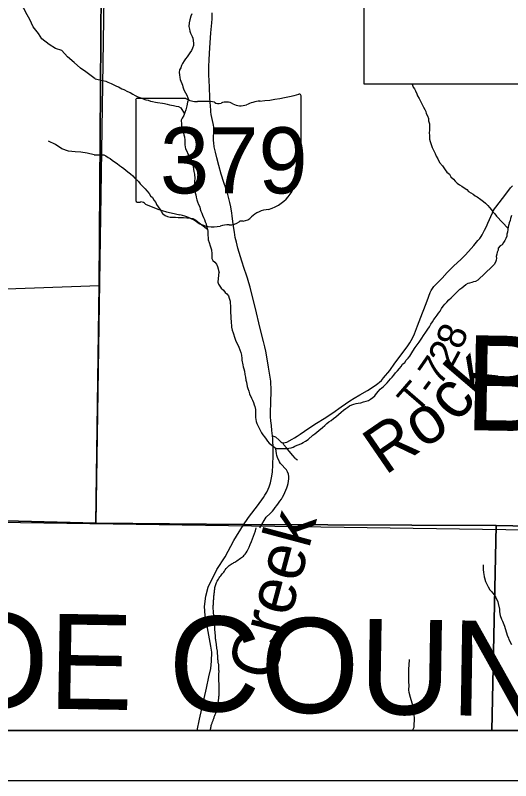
# Model space of a CAD drawing. Extents: x 0 to 34, y 0 to 22.
# Drawn here: x 26.845 to 27.832, y 14 to 15.526 of the extents above; entities that cross this region are included whole.
import ezdxf

# ---------------------------------------------------------------- set-up
doc = ezdxf.new("R2010")
doc.units = 0
for name, color, linetype in [('GM_X_Corporation', 7, 'Continuous'), ('GM_X_County', 7, 'Continuous'), ('GM_X_County_Text', 7, 'Continuous'), ('GM_X_Minor_River', 7, 'Continuous'), ('GM_X_Minor_River_Text', 7, 'Continuous'), ('GM_X_State_Route', 7, 'Continuous'), ('GM_X_State_Shield', 7, 'Continuous'), ('GM_X_Township_Road', 7, 'Continuous'), ('GM_X_Township_Road_Text', 7, 'Continuous'), ('SH_Data', 7, 'Continuous')]:
    doc.layers.add(name, color=color, linetype=linetype)

msp = doc.modelspace()

# ---------------------------------------------------------------- linework, layer by layer
at = {"layer": 'GM_X_Corporation'}
for points in [[(30.3167, 20.9), (27.1022, 20.9), (27.0898, 20.417), (27.0897, 20.4135), (27.089, 20.3692), (27.0873, 20.2665), (27.0907, 20.123), (27.0885, 20.1139), (27.0864, 20.0138), (27.0761, 19.6806), (27.0733, 19.498), (27.0719, 19.3912), (27.0487, 18.5805), (27.0419, 17.8236), (27.0349, 17.5522), (27.0234, 16.6611), (27.0124, 14.988), (27.0057, 14.5136), (27.2999, 14.5107), (27.8031, 14.5091), (28.4032, 14.497)], [(29.5503, 20.3788), (27.6751, 20.4106), (27.5829, 20.4116), (27.2336, 20.4152), (27.1239, 20.4163), (27.0898, 20.417), (27.0897, 20.4135), (27.089, 20.3692), (27.0873, 20.2665), (27.0907, 20.123), (27.0885, 20.1139), (27.0864, 20.0138), (27.0761, 19.6806), (27.0733, 19.498), (27.0719, 19.3912), (27.0487, 18.5805), (27.0419, 17.8236), (27.0349, 17.5522), (27.0234, 16.6611), (27.0124, 14.988), (27.0057, 14.5136), (27.2999, 14.5107), (27.8031, 14.5091), (28.4032, 14.497)], [(23.5167, 20.3276), (23.5167, 14.5642), (23.7464, 14.562), (24.4108, 14.5557), (24.414, 14.5556), (24.9788, 14.5503), (25.0494, 14.5496), (25.56, 14.5392), (26.009, 14.53), (26.3333, 14.5233), (26.7998, 14.5186), (27.0057, 14.5136), (27.0124, 14.988), (27.0234, 16.6611), (27.0349, 17.5522)], [(23.5167, 20.3276), (23.5167, 14.5642), (23.7464, 14.562), (24.4108, 14.5557), (24.414, 14.5556), (24.9788, 14.5503), (25.0494, 14.5496), (25.56, 14.5392), (26.009, 14.53), (26.3333, 14.5233), (26.7998, 14.5186), (27.0057, 14.5136), (27.0124, 14.988), (27.0234, 16.6611), (27.0349, 17.5522)]]:
    msp.add_lwpolyline(points, dxfattribs=at)
for points in [[(23.5167, 14.5642), (23.5167, 14.1), (30.3167, 14.1), (30.3167, 14.4639), (30.3098, 14.464), (29.2367, 14.4822), (29.1713, 14.4832), (28.7853, 14.4893), (28.4032, 14.497), (27.8031, 14.5091), (27.2999, 14.5107), (27.0057, 14.5136), (26.7998, 14.5186), (26.3333, 14.5233), (26.009, 14.53), (25.56, 14.5392), (25.0494, 14.5496), (24.9788, 14.5503), (24.414, 14.5556), (24.4108, 14.5557), (23.7464, 14.562)], [(23.5167, 14.5642), (23.5167, 14.1), (27.795, 14.1), (27.8031, 14.5091), (27.2999, 14.5107), (27.0057, 14.5136), (26.7998, 14.5186), (26.3333, 14.5233), (26.009, 14.53), (25.56, 14.5392), (25.0494, 14.5496), (24.9788, 14.5503), (24.414, 14.5556), (24.4108, 14.5557), (23.7464, 14.562)], [(27.795, 14.1), (30.3167, 14.1), (30.3167, 14.4639), (30.3098, 14.464), (29.2367, 14.4822), (29.1713, 14.4832), (28.7853, 14.4893), (28.4032, 14.497), (27.8031, 14.5091)]]:
    msp.add_lwpolyline(points, close=True, dxfattribs=at)
at = {"layer": 'GM_X_County'}
for p, q in [((27.1022, 20.9), (27.0057, 14.5136)), ((23.5167, 14.5642), (30.3167, 14.4639))]:
    msp.add_line(p, q, dxfattribs=at)
at = {"layer": 'GM_X_Minor_River'}
for points in [[(27.0043, 15.3997), (26.9854, 15.4131), (26.975, 15.4209), (26.9624, 15.4322), (26.949, 15.4434), (26.9376, 15.4557), (26.9254, 15.4601), (26.9124, 15.4679), (26.8983, 15.4795), (26.8914, 15.4896), (26.8806, 15.5032), (26.874, 15.5175), (26.869, 15.5273), (26.8616, 15.5408), (26.8536, 15.5506)], [(27.1969, 15.5291), (27.1951, 15.5241), (27.1933, 15.5169), (27.1919, 15.5108), (27.1912, 15.5036), (27.1921, 15.4983), (27.1933, 15.4945), (27.1945, 15.4904), (27.1973, 15.484), (27.1988, 15.4802), (27.2005, 15.4708), (27.2002, 15.4659), (27.1984, 15.4609), (27.1962, 15.4556), (27.1929, 15.4513), (27.1874, 15.4436), (27.1844, 15.4394), (27.1818, 15.4356), (27.1781, 15.4302), (27.1763, 15.426), (27.1749, 15.4214), (27.1727, 15.4176), (27.1716, 15.4119), (27.1721, 15.4077), (27.173, 15.4021), (27.1738, 15.3983), (27.1781, 15.387), (27.179, 15.3832), (27.181, 15.3772), (27.1841, 15.3716), (27.1872, 15.3667), (27.1892, 15.3618), (27.1904, 15.358), (27.1886, 15.3531), (27.1868, 15.3458), (27.185, 15.3375), (27.1832, 15.3321), (27.1811, 15.3264), (27.1778, 15.3207), (27.1759, 15.3168), (27.1761, 15.3089), (27.1765, 15.3047), (27.1777, 15.3009), (27.1789, 15.2968), (27.181, 15.2877), (27.1822, 15.2836), (27.1827, 15.2772), (27.1831, 15.2726), (27.1832, 15.2681), (27.1841, 15.2601), (27.1869, 15.2549), (27.1892, 15.2496), (27.1916, 15.2458), (27.1943, 15.2417), (27.1967, 15.2349), (27.1987, 15.2285), (27.1995, 15.2248), (27.2003, 15.2191), (27.2012, 15.2146), (27.202, 15.2093), (27.2029, 15.2006), (27.2026, 15.1956), (27.202, 15.1884), (27.2029, 15.1816), (27.2033, 15.1778), (27.2038, 15.1721), (27.205, 15.168), (27.2055, 15.1635), (27.2071, 15.1582), (27.2083, 15.154), (27.2103, 15.1488), (27.2126, 15.1442), (27.2135, 15.1397), (27.215, 15.1356)], [(27.0043, 15.3997), (27.0198, 15.396), (27.0255, 15.3946), (27.0293, 15.3931), (27.0362, 15.3898), (27.0469, 15.3851), (27.0511, 15.3833), (27.0576, 15.3796), (27.0614, 15.3781), (27.0686, 15.3745), (27.0743, 15.3719), (27.0793, 15.369), (27.0839, 15.3664), (27.0896, 15.3638), (27.0953, 15.3613), (27.0999, 15.3595), (27.1052, 15.3577), (27.1098, 15.3566), (27.1144, 15.3552), (27.1185, 15.3545), (27.1246, 15.3531), (27.1284, 15.3524), (27.1387, 15.3507), (27.1428, 15.3504), (27.1478, 15.3489), (27.1527, 15.3479), (27.1565, 15.3472), (27.1607, 15.3461), (27.1656, 15.3451), (27.1706, 15.344), (27.1748, 15.3415), (27.1823, 15.3296)], [(27.6357, 15.3888), (27.6367, 15.3871), (27.638, 15.383), (27.6407, 15.3792), (27.6426, 15.3755), (27.645, 15.3698), (27.6466, 15.3657), (27.6497, 15.36), (27.6528, 15.3548), (27.6548, 15.3507), (27.6587, 15.3431), (27.6611, 15.3383), (27.663, 15.3345), (27.6642, 15.33), (27.6669, 15.3258), (27.6686, 15.3202), (27.6686, 15.3156), (27.6703, 15.3096), (27.6707, 15.3058), (27.6708, 15.3013), (27.6705, 15.2963), (27.6702, 15.2922), (27.6703, 15.2861), (27.6704, 15.2793), (27.672, 15.2748), (27.6732, 15.2702), (27.6756, 15.2623), (27.6819, 15.2503), (27.6839, 15.245), (27.687, 15.2398), (27.6905, 15.2323), (27.6967, 15.2263), (27.7021, 15.218), (27.7052, 15.2132), (27.7102, 15.2091), (27.7133, 15.2038), (27.7183, 15.1994), (27.7214, 15.1956), (27.7257, 15.1916), (27.7306, 15.1882), (27.7348, 15.1856), (27.7394, 15.1823), (27.7448, 15.1786), (27.7486, 15.1749), (27.7578, 15.1697), (27.7617, 15.166), (27.7655, 15.1642), (27.7728, 15.159), (27.7781, 15.1546), (27.7824, 15.1512)], [(27.0026, 15.248), (26.9885, 15.2509), (26.976, 15.253), (26.9642, 15.254), (26.951, 15.2554), (26.9377, 15.2598), (26.9251, 15.2683), (26.9114, 15.275)], [(27.0026, 15.248), (27.0216, 15.2478), (27.0254, 15.2456), (27.03, 15.2423), (27.0339, 15.2404), (27.0385, 15.2371), (27.0427, 15.2341), (27.0484, 15.2304), (27.053, 15.2267), (27.0569, 15.2238), (27.0614, 15.2208), (27.0657, 15.2175), (27.0695, 15.2141), (27.0749, 15.2097), (27.0791, 15.2063), (27.083, 15.2022), (27.091, 15.1944), (27.0941, 15.1903), (27.0984, 15.1855), (27.1038, 15.1799), (27.1076, 15.1758), (27.1119, 15.1709), (27.1146, 15.166), (27.1185, 15.1627), (27.1216, 15.1571), (27.1254, 15.1526), (27.1266, 15.1488), (27.1297, 15.1443), (27.1329, 15.1394), (27.1356, 15.1353), (27.1387, 15.1312), (27.1437, 15.1267), (27.1482, 15.1249), (27.1536, 15.1239), (27.1596, 15.1236), (27.1642, 15.1233), (27.1695, 15.123), (27.1804, 15.1232), (27.1869, 15.1226), (27.1907, 15.1226), (27.1948, 15.1219), (27.199, 15.1209), (27.2032, 15.1187), (27.228, 15.0996)], [(27.7824, 15.1512), (27.7866, 15.1471), (27.7901, 15.143), (27.7939, 15.1385), (27.797, 15.134), (27.8005, 15.1303), (27.804, 15.1255), (27.827, 15.1007)], [(27.215, 15.1356), (27.2166, 15.1314), (27.2182, 15.1277), (27.2202, 15.1232), (27.2225, 15.119), (27.2237, 15.1141), (27.2253, 15.11), (27.2265, 15.1054), (27.2277, 15.1017), (27.2286, 15.0956), (27.2287, 15.0915), (27.2291, 15.0869), (27.2292, 15.0831), (27.2296, 15.0786), (27.2316, 15.0733), (27.2336, 15.0665), (27.2361, 15.0582), (27.2366, 15.0507), (27.2367, 15.0454), (27.2371, 15.0412), (27.2387, 15.0374), (27.2429, 15.0337), (27.2464, 15.03), (27.2484, 15.0255), (27.2496, 15.0209), (27.25, 15.0172), (27.2516, 15.013)], [(27.8339, 15.1267), (27.8317, 15.121), (27.831, 15.1168), (27.8296, 15.1126), (27.8289, 15.1088), (27.8274, 15.1043), (27.8268, 15.0993), (27.8257, 15.094), (27.825, 15.0898), (27.8244, 15.086), (27.8229, 15.0814), (27.8207, 15.0768), (27.8181, 15.073), (27.8156, 15.0684), (27.8114, 15.0664), (27.8077, 15.0618), (27.8071, 15.0577), (27.8052, 15.0538), (27.8045, 15.05), (27.8035, 15.0455), (27.8039, 15.0417), (27.8036, 15.0379), (27.8018, 15.0337), (27.7992, 15.0295), (27.7951, 15.0248)], [(27.6735, 14.9101), (27.6768, 14.9147), (27.6791, 14.9193), (27.6821, 14.9231), (27.6858, 14.9281), (27.6884, 14.9319), (27.6918, 14.9365), (27.6944, 14.9414), (27.6981, 14.946), (27.7011, 14.9502), (27.7053, 14.9541), (27.7094, 14.9587), (27.7139, 14.9629), (27.7222, 14.9713), (27.7312, 14.9798), (27.7349, 14.9828), (27.7387, 14.9863), (27.7428, 14.9894), (27.7474, 14.9921), (27.7511, 14.9929), (27.7553, 14.994), (27.7591, 14.9952), (27.7629, 14.996), (27.7674, 14.9987), (27.7951, 15.0248)], [(27.251, 15.0145), (27.2486, 14.994), (27.2502, 14.9899), (27.2525, 14.9861), (27.2552, 14.9823), (27.2598, 14.9778), (27.2632, 14.9737), (27.267, 14.9707), (27.2697, 14.9669), (27.2716, 14.9623), (27.2732, 14.9563), (27.2736, 14.9525), (27.274, 14.9464), (27.2741, 14.9373), (27.2741, 14.9331), (27.2746, 14.9266), (27.275, 14.9209), (27.2754, 14.916), (27.2763, 14.9042), (27.2771, 14.8982), (27.279, 14.8929), (27.2825, 14.8826), (27.2848, 14.8766), (27.2879, 14.8705), (27.2903, 14.8645), (27.2929, 14.8592), (27.2949, 14.8539), (27.2961, 14.8482), (27.2965, 14.8421), (27.2969, 14.8383), (27.2985, 14.8292), (27.2993, 14.825), (27.3005, 14.8212), (27.3016, 14.8163), (27.3028, 14.8102), (27.304, 14.8049), (27.3048, 14.7985), (27.3056, 14.7947), (27.3072, 14.7863), (27.3088, 14.7818), (27.3103, 14.7765), (27.3122, 14.7716), (27.3161, 14.7625), (27.3177, 14.7587), (27.3196, 14.7542), (27.3211, 14.7496), (27.3223, 14.7458), (27.3235, 14.7398), (27.3239, 14.736), (27.324, 14.7242), (27.3244, 14.72), (27.3252, 14.7162), (27.3268, 14.7121), (27.3283, 14.7079), (27.3302, 14.7041), (27.336, 14.6935), (27.3383, 14.6897), (27.3418, 14.6856), (27.3452, 14.6811), (27.3479, 14.6773), (27.3509, 14.6731), (27.3647, 14.6626)], [(27.3322, 14.504), (27.3454, 14.5253), (27.3533, 14.5326), (27.3574, 14.5372), (27.3604, 14.541), (27.363, 14.5448), (27.3664, 14.549), (27.3694, 14.5532), (27.3724, 14.5571), (27.3754, 14.5616), (27.3776, 14.5655), (27.3802, 14.57), (27.3825, 14.5746), (27.3843, 14.5796), (27.3862, 14.5842), (27.3873, 14.588), (27.3887, 14.5925), (27.3898, 14.5975), (27.3902, 14.6017), (27.3901, 14.6066), (27.3897, 14.6112), (27.3878, 14.6157), (27.3855, 14.6195), (27.3736, 14.6323), (27.3717, 14.6361), (27.3679, 14.6444), (27.3663, 14.6486), (27.3655, 14.6527), (27.3651, 14.6573), (27.3643, 14.6619), (27.3643, 14.6626), (27.373, 14.6623), (27.3859, 14.6624), (27.3904, 14.6628), (27.3946, 14.6636), (27.3987, 14.6652), (27.4025, 14.6668), (27.4067, 14.6687), (27.4108, 14.6703), (27.4153, 14.6726), (27.4191, 14.6741), (27.4236, 14.6768), (27.4285, 14.6803), (27.4383, 14.6887), (27.4421, 14.6914), (27.4462, 14.6949), (27.4499, 14.6983), (27.4575, 14.7045), (27.462, 14.7083), (27.4661, 14.7122), (27.4699, 14.7152), (27.4748, 14.7183), (27.4793, 14.7222), (27.4838, 14.7256), (27.4891, 14.7302), (27.4943, 14.7345), (27.4992, 14.7387), (27.5037, 14.7418), (27.5075, 14.7448), (27.5113, 14.7475), (27.5158, 14.7495), (27.5199, 14.751), (27.5241, 14.7518), (27.5286, 14.7526), (27.5335, 14.7534), (27.5392, 14.7554), (27.5445, 14.7569), (27.549, 14.7581), (27.5528, 14.7604), (27.5577, 14.7643), (27.5614, 14.7677), (27.5648, 14.772), (27.5689, 14.7765), (27.5723, 14.7808), (27.5787, 14.7861), (27.5825, 14.7896), (27.5862, 14.7934), (27.5896, 14.7973), (27.5926, 14.8011), (27.5963, 14.8049), (27.5993, 14.8087), (27.6031, 14.8133), (27.6065, 14.8172), (27.6106, 14.8218), (27.614, 14.8256), (27.617, 14.8302), (27.6215, 14.834), (27.6241, 14.8382), (27.6282, 14.8424), (27.6312, 14.8466), (27.6353, 14.8528), (27.6376, 14.8566), (27.6417, 14.8635), (27.6462, 14.8688), (27.6503, 14.8746), (27.6555, 14.8822), (27.6589, 14.8875), (27.6634, 14.8944), (27.6671, 14.9005), (27.6705, 14.9051), (27.6735, 14.9101)], [(27.7778, 14.4304), (27.7777, 14.4217), (27.7785, 14.4145), (27.7788, 14.4115), (27.7795, 14.4065), (27.7803, 14.4042), (27.7821, 14.397), (27.7836, 14.3943), (27.7859, 14.3894), (27.7878, 14.3863), (27.7911, 14.3806), (27.7949, 14.3768), (27.796, 14.3745), (27.7994, 14.3703), (27.8028, 14.3653), (27.8065, 14.3566), (27.8077, 14.3532), (27.8099, 14.3421), (27.8102, 14.3364), (27.8117, 14.3296), (27.8143, 14.322), (27.8158, 14.3178), (27.8199, 14.3079), (27.8214, 14.3037), (27.824, 14.2949), (27.8255, 14.2904), (27.8281, 14.2843), (27.8288, 14.2812), (27.8337, 14.2717)], [(27.6301, 14.2419), (27.6301, 14.2381), (27.6297, 14.2336), (27.6296, 14.2302), (27.6288, 14.2233), (27.6284, 14.2203), (27.6284, 14.2082), (27.629, 14.1964), (27.6294, 14.1903), (27.6289, 14.1808), (27.6297, 14.1762), (27.6323, 14.1663), (27.6334, 14.1618), (27.636, 14.153), (27.6371, 14.1504), (27.6378, 14.1435), (27.6378, 14.1405), (27.6385, 14.1355), (27.6393, 14.1314), (27.64, 14.1245), (27.6403, 14.1215), (27.6395, 14.1112), (27.6391, 14.1063), (27.6375, 14.1021), (27.6374, 14.1)]]:
    msp.add_lwpolyline(points, dxfattribs=at)
msp.add_spline([(27.2396, 14.3458), (27.2399, 14.353), (27.2406, 14.3621), (27.2413, 14.3704), (27.242, 14.378), (27.2431, 14.3853), (27.2453, 14.3929), (27.2498, 14.402), (27.2562, 14.4104), (27.2618, 14.4177), (27.2697, 14.4276), (27.2773, 14.4329), (27.2845, 14.4368), (27.2939, 14.4437), (27.3014, 14.4494), (27.3086, 14.4605), (27.3254, 14.504)], degree=3, dxfattribs=at)
msp.add_open_spline([(27.2334, 14.1), (27.2335, 14.1003), (27.2336, 14.1005), (27.2337, 14.1008), (27.2348, 14.1044), (27.235, 14.1083), (27.2362, 14.1119), (27.2372, 14.1145), (27.2383, 14.1172), (27.2392, 14.1198), (27.2402, 14.1228), (27.2412, 14.1257), (27.2422, 14.1286), (27.2433, 14.1318), (27.2449, 14.1348), (27.2459, 14.1381), (27.2468, 14.1409), (27.2473, 14.1437), (27.2478, 14.1465), (27.2484, 14.15), (27.249, 14.1536), (27.2496, 14.1571), (27.25, 14.1596), (27.2504, 14.1622), (27.2507, 14.1647), (27.251, 14.1681), (27.2512, 14.1716), (27.2514, 14.175), (27.2515, 14.1779), (27.2516, 14.1808), (27.2517, 14.1837), (27.2517, 14.1861), (27.2517, 14.1885), (27.2516, 14.1909), (27.2515, 14.1936), (27.2509, 14.1962), (27.2508, 14.1989), (27.2507, 14.2017), (27.2507, 14.2045), (27.2508, 14.2072), (27.2508, 14.2099), (27.251, 14.2126), (27.2511, 14.2152), (27.2511, 14.2176), (27.2511, 14.22), (27.251, 14.2224), (27.251, 14.2251), (27.2508, 14.2278), (27.2506, 14.2304), (27.2504, 14.2328), (27.2496, 14.2352), (27.2494, 14.2376), (27.2491, 14.2414), (27.2488, 14.2452), (27.2486, 14.249), (27.2484, 14.2515), (27.2484, 14.2541), (27.2481, 14.2566), (27.2479, 14.2591), (27.2473, 14.2616), (27.2469, 14.2642), (27.2465, 14.2671), (27.2462, 14.27), (27.2458, 14.2729), (27.2454, 14.2754), (27.2449, 14.2779), (27.2446, 14.2805), (27.244, 14.2845), (27.2441, 14.2886), (27.2437, 14.2926), (27.2435, 14.295), (27.2431, 14.2974), (27.2429, 14.2998), (27.2427, 14.3027), (27.2431, 14.3057), (27.2428, 14.3086), (27.2426, 14.3115), (27.2423, 14.3144), (27.242, 14.3173), (27.2417, 14.3205), (27.2415, 14.3236), (27.2412, 14.3268), (27.2409, 14.3297), (27.2401, 14.3326), (27.24, 14.3355), (27.2399, 14.3389), (27.2397, 14.3423), (27.2396, 14.3458)], degree=3, dxfattribs=at)
at = {"layer": 'GM_X_State_Route'}
for points in [[(27.3001, 14.5101), (27.3083, 14.5228), (27.3119, 14.5276), (27.3277, 14.5483), (27.3399, 14.5648), (27.3427, 14.5691), (27.3461, 14.5751), (27.3492, 14.5813), (27.3512, 14.5861), (27.3525, 14.59), (27.3536, 14.5937), (27.3553, 14.6007), (27.3564, 14.6075), (27.3574, 14.616), (27.3582, 14.6292), (27.3589, 14.6492), (27.359, 14.6587), (27.3588, 14.668), (27.3585, 14.6751), (27.3581, 14.6821), (27.3575, 14.6878), (27.3565, 14.6985), (27.3554, 14.7084), (27.3546, 14.7173), (27.354, 14.7256), (27.3538, 14.739), (27.3541, 14.7496), (27.3546, 14.7599), (27.355, 14.7711), (27.3549, 14.7779), (27.3541, 14.7964), (27.3518, 14.8125), (27.3499, 14.8247), (27.3485, 14.8331), (27.3442, 14.8566), (27.3423, 14.865), (27.3395, 14.8755), (27.3346, 14.8963), (27.3304, 14.9129), (27.3255, 14.9331), (27.3132, 14.984), (27.3108, 14.9927), (27.3079, 15.0018), (27.3059, 15.008), (27.301, 15.0214), (27.2964, 15.036), (27.2888, 15.0621), (27.2857, 15.0738), (27.2836, 15.0833), (27.2817, 15.094), (27.2806, 15.1013), (27.2787, 15.1152), (27.2772, 15.1265), (27.2766, 15.1315), (27.2748, 15.1439), (27.2729, 15.153), (27.2709, 15.161), (27.2678, 15.1713), (27.2646, 15.1814), (27.2607, 15.1926), (27.2554, 15.2092), (27.2507, 15.2266), (27.2467, 15.2416), (27.2438, 15.2531), (27.2426, 15.2585), (27.2416, 15.264), (27.2407, 15.2717), (27.2404, 15.2768), (27.2403, 15.2791), (27.241, 15.298), (27.2407, 15.3031), (27.2403, 15.3072), (27.2398, 15.3107), (27.2358, 15.3285), (27.235, 15.3334), (27.2345, 15.3371), (27.233, 15.361), (27.2319, 15.3832), (27.2308, 15.4071), (27.231, 15.4236), (27.2314, 15.4378), (27.2329, 15.4612), (27.2349, 15.491), (27.2367, 15.5111), (27.2373, 15.5193), (27.2374, 15.5237), (27.2372, 15.5309)], [(27.2076, 14.1), (27.2123, 14.1224), (27.2263, 14.1847), (27.2311, 14.2071), (27.2347, 14.2239), (27.236, 14.238), (27.2368, 14.2562), (27.2351, 14.2685), (27.2281, 14.3047), (27.2235, 14.3294), (27.2224, 14.3472), (27.2248, 14.3676), (27.2294, 14.3856), (27.2469, 14.4209), (27.2632, 14.4463), (27.2809, 14.479), (27.3001, 14.5101)]]:
    msp.add_lwpolyline(points, dxfattribs=at)
at = {"layer": 'GM_X_State_Shield'}
for p, q in [((27.0851, 15.357), (27.0851, 15.1569)), ((27.1848, 15.3605), (27.0883, 15.3605)), ((27.4146, 15.2607), (27.4146, 15.3654)), ((27.4146, 15.2608), (27.4146, 15.2607))]:
    msp.add_line(p, q, dxfattribs=at)
for centre, major_axis, start_param, end_param in [((27.2972, 15.6333), (0.3495, 0), 4.814394, 5.042369), ((27.411, 15.3659), (0.00367, 0), 6.141152, 7.989035), ((27.0888, 15.3575), (0.00382, 0), 1.712693, 3.28349), ((27.2078, 15.3837), (0.037, 0), 4.042523, 4.731795), ((27.2201, 15.2481), (0.133, 0), 1.404758, 1.657858), ((27.2503, 15.3585), (0.0107, 0), 3.836095, 5.185415), ((27.266, 15.3354), (0.0222, 0), 0.950623, 2.079405), ((27.3418, 15.2993), (0.0703, 0), 1.699011, 2.107814), ((27.2946, 15.3671), (0.0267, 0), 4.081561, 5.145723), ((27.4138, 15.2531), (0.00568, 0), 1.883978, 3.671073), ((27.3777, 15.2398), (0.0341, 0), 5.934695, 6.695948), ((27.4107, 15.2603), (0.00393, 0), 5.05454, 6.418171), ((27.4278, 15.2169), (0.0248, 0), 2.387724, 3.262537), ((27.3168, 15.2036), (0.0874, 0), 5.101752, 6.440018), ((27.0889, 15.1565), (0.00385, 0), 3.00124, 4.508301), ((27.0895, 15.1769), (0.0294, 0), 4.665946, 4.897461), ((27.0955, 15.1454), (0.0106, 0), 0.519207, 1.627899), ((27.2293, 15.3252), (0.2524, 0), 4.195997, 4.488961), ((27.154, 15.067), (0.079, 0), 0.823519, 1.323587), ((27.293, 15.1375), (0.0282, 0), 4.937069, 5.64225), ((27.3537, 15.1007), (0.0479, 0), 1.647645, 2.488434), ((27.2395, 15.1444), (0.0501, 0), 4.026481, 4.996735), ((27.2721, 15.1294), (0.0267, 0), 4.691044, 5.507374), ((27.2962, 15.11), (0.00752, 0), 1.147584, 2.315152), ((27.2684, 15.0752), (0.0412, 0), 1.495662, 1.94098)]:
    msp.add_ellipse(centre, major_axis=major_axis, ratio=0.8, start_param=start_param, end_param=end_param, dxfattribs=at)
at = {"layer": 'GM_X_Township_Road'}
msp.add_line((26.6231, 14.973), (27.0126, 14.9875), dxfattribs=at)
for points in [[(27.3575, 14.6878), (27.3597, 14.6872), (27.3617, 14.6864), (27.3634, 14.6853), (27.3708, 14.6788), (27.3742, 14.6756), (27.3761, 14.6742), (27.3776, 14.6738), (27.3793, 14.6735), (27.3829, 14.674), (27.3862, 14.6753), (27.3971, 14.6811), (27.4013, 14.6836), (27.4067, 14.6869), (27.4126, 14.6908), (27.4299, 14.7027), (27.4456, 14.7127), (27.4608, 14.7224), (27.4778, 14.7338), (27.4943, 14.7455), (27.5121, 14.7575), (27.5203, 14.7624), (27.5317, 14.7692), (27.5467, 14.7783), (27.5626, 14.7881), (27.5677, 14.7918), (27.5712, 14.7948), (27.5746, 14.7979), (27.5791, 14.803), (27.5914, 14.8181), (27.6018, 14.8323), (27.612, 14.8466), (27.6274, 14.867), (27.6315, 14.8729), (27.6342, 14.8775), (27.6375, 14.8839), (27.6406, 14.8909), (27.6466, 14.9067), (27.6534, 14.9242), (27.6567, 14.9331), (27.659, 14.9394), (27.6659, 14.9568), (27.6719, 14.9732), (27.6739, 14.9775), (27.6764, 14.9816), (27.6793, 14.9853), (27.6827, 14.989), (27.6855, 14.9916), (27.6956, 15.0021), (27.7061, 15.0133), (27.7193, 15.0264), (27.7332, 15.0393), (27.7419, 15.0481), (27.7485, 15.0553), (27.7586, 15.0671), (27.767, 15.0771), (27.7706, 15.0814), (27.7735, 15.0853), (27.7753, 15.0881), (27.7776, 15.0923), (27.7803, 15.0975), (27.7839, 15.105), (27.787, 15.1116), (27.796, 15.1323), (27.797, 15.1346), (27.7984, 15.1372), (27.8001, 15.1401), (27.8025, 15.1436), (27.816, 15.161), (27.8249, 15.1723), (27.8323, 15.1818), (27.8362, 15.1864)], [(27.4082, 14.6389), (27.4063, 14.6397), (27.4053, 14.6404), (27.4038, 14.6417), (27.4026, 14.643), (27.398, 14.6485), (27.3911, 14.6569), (27.3855, 14.6636), (27.3803, 14.6699), (27.3797, 14.6709), (27.3794, 14.6719), (27.3793, 14.6735)]]:
    msp.add_lwpolyline(points, dxfattribs=at)
at = {"layer": 'SH_Data'}
for points in [[(23.4167, 21), (30.4167, 21), (30.4167, 14), (23.4167, 14)], [(23.5167, 20.9), (30.3167, 20.9), (30.3167, 14.1), (23.5167, 14.1)], [(27.5407, 16.0188), (28.8122, 16.0188), (28.8122, 15.3888), (27.5407, 15.3888)]]:
    msp.add_lwpolyline(points, close=True, dxfattribs=at)

# ---------------------------------------------------------------- texts
at = {"layer": 'GM_X_County_Text'}
for s, rotation, p in [('BELMONT COUNTY', 358.998, (27.7391, 14.6991)), ('MONROE COUNTY', 359.0616, (25.9393, 14.1595))]:
    msp.add_text(s, height=0.189394, rotation=rotation, dxfattribs=at).set_placement(p)
at = {"layer": 'GM_X_Minor_River_Text'}
for s, height, rotation, p in [('ck', 0.09468, 49.4309, (27.7255, 14.7116)), ('Ro', 0.09469, 34.431, (27.582, 14.6079)), ('Creek', 0.09467, 74.9921, (27.3591, 14.1959))]:
    msp.add_text(s, height=height, rotation=rotation, dxfattribs=at).set_placement(p)
at = {"layer": 'GM_X_State_Shield'}
msp.add_text('379', height=0.13184, dxfattribs=at).set_placement((27.1335, 15.171))
at = {"layer": 'GM_X_Township_Road_Text'}
for s, rotation, p in [('8', 68.2327, (27.7337, 14.8572)), ('2', 62.0325, (27.7145, 14.8202)), ('7', 55.3442, (27.6908, 14.7852)), ('T', 49.1235, (27.645, 14.729)), ('-', 53.5433, (27.6758, 14.7649))]:
    msp.add_text(s, height=0.0568, rotation=rotation, dxfattribs=at).set_placement(p)

doc.saveas('drawing.dxf')
